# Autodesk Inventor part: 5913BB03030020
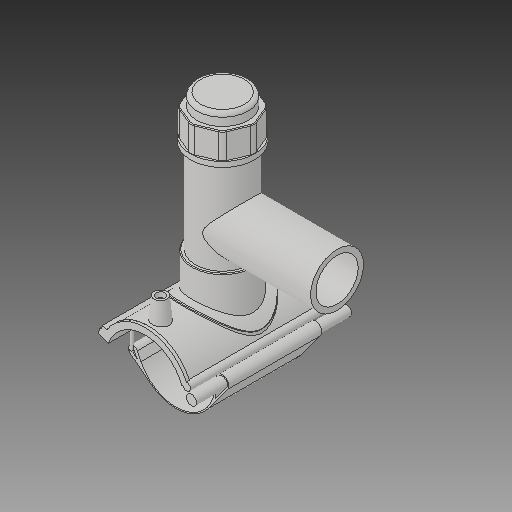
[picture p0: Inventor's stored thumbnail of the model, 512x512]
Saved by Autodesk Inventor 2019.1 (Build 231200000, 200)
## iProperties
Created: 2017-07
Part Number: 5913BB03030020
Material: Generic
Description: PLASSON TAPPING SADDLE 3''IPS x 2''IPS
Document SubType Name: Modeling
Designer: KIM
Mass: 1712.7 g
Surface Area: 2671.49 cm^2
Volume: 1712.7 cm^3
Density: 1 g/cm^3
Appearance: Default
Author: KIM
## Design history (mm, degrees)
derived "5913B.ipt"
feature "Solid1::5913B.ipt"
feature "Solid2::5913B.ipt"
feature "Solid4::5913B.ipt"
feature "Solid5::5913B.ipt"
tag "TaggingFeature1"
body "Solid1"
body "Solid2"
other parameters: "d0" = 88.7, "d2" = 208.407, "d3" = 22.175, "d4" = 176.022, "d5" = 0, "d6" = 0.1, "d8" = 0, "d40" = 52.58136, "d41" = 88.7, "d43" = 0, "d45" = 0, "d47" = 156.1722, "d78" = 74.35, "d79" = 15, "d80" = 70.4088, "d82" = 5 deg, "d84" = 4, "d85" = 14, "d86" = 0, "d87" = 3, "d88" = 0, "d96" = 103.14036, "d97" = 3.52044, "d98" = 0, "d102" = 0.887, "d120" = 140 deg, "d121" = 24.228, "d122" = 20 deg, "d123" = 252.795, "d124" = 60.6708, "d126" = 0, "d153" = 176.022, "d154" = 0, "d159" = 2.4836, "d162" = 105.6132, "d163" = 0, "d164" = 44.35, "d169" = 4.0905, "d170" = 3.7254, "d172" = 0, "d173" = 1, "d175" = 44.35, "d176" = 20 deg, "d177" = 6.209, "d178" = 12.418, "d180" = 0, "d183" = 4.9672, "d184" = 4.9672, "d187" = 50.559, "d188" = 3.7254, "d189" = 6.209, "d190" = 0, "d191" = 75.8385, "d193" = 3.1932, "d194" = 1.5966, "d195" = 90 deg, "d197" = 0, "d199" = 0, "d200" = 6.209, "d202" = 0, "d203" = 194.818, "d204" = 69.0973, "d205" = 50.9138, "d206" = 61.8239, "d207" = 146.1135, "d208" = 151.95804, "d209" = 181.18074, "d210" = 62.55124, "d211" = 72.734, "d212" = 58.1872, "d213" = 40.392, "d216" = 0, "d217" = 8.87, "d218" = 4.435, "d219" = 0.887, "d222" = 88.7, "d224" = 0, "d230" = 0.887, "d257" = 119.28, "d258" = 129.794, "d259" = 48.08, "d260" = 60.1, "d263" = 138.938, "d265" = 0, "d267" = 13.00006, "d268" = 2.60001, "d269" = 2.60001, "d271" = 2.60001, "d273" = 0, "d274" = 23.56194, "d275" = 70.96, "d277" = 35.48, "d278" = 141.92, "d280" = 0, "d281" = 88.7, "d283" = 0, "d285" = 0, "d290" = 8.87, "d291" = 11.531, "d293" = 48.785, "d294" = 45.6805, "d296" = 13.305, "d297" = 10.644, "d_" = 88.7, "B_" = 138.938, "L_" = 176.022, "d_t" = 6, "H_2" = 194.818, "H_1" = 74.93, "d_1" = 60.1, "H_" = 129.794, "d1" = 101.118, "d192" = 3.1932
